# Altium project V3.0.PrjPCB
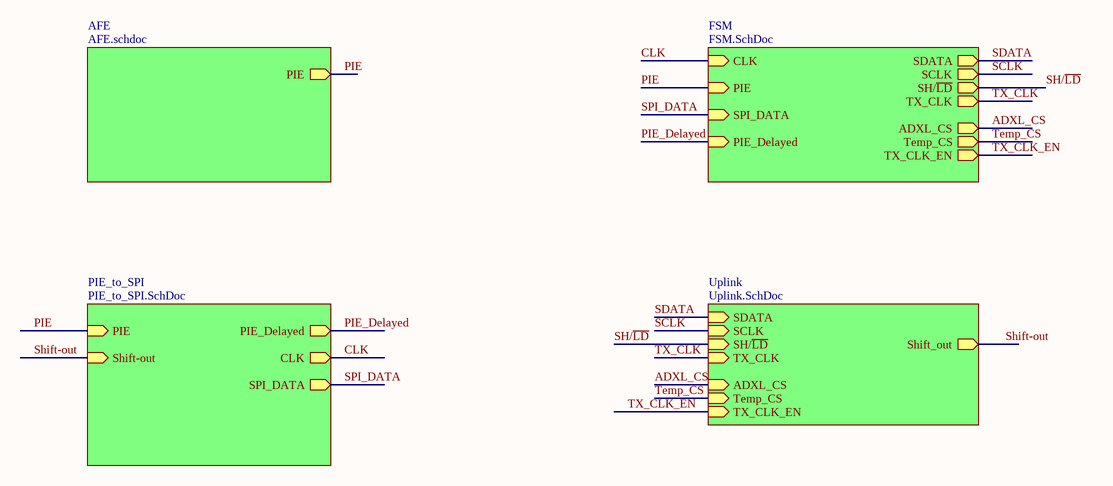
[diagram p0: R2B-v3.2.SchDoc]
5 sheets, 119 parts. Net scope: hierarchical (ports join the sheet entries above them; power ports are global).
Board file: 10.17.PcbDoc
Sheets:
  R2B-v3.2.SchDoc
    AFE = AFE.schdoc
    PIE_to_SPI = PIE_to_SPI.SchDoc
    FSM = FSM.SchDoc
    Uplink = Uplink.SchDoc

## Sheet R2B-v3.2.SchDoc
size A4; Date: 2019-11-16; Address1: Chong Zhang; Address2: Yihang Song; Revision: 3.2; SheetNumber: 1; SheetTotal: 5; Author1: Chong Zhang; Author2: Yihang Song

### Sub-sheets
AFE = AFE.schdoc: PIE (out)
FSM = FSM.SchDoc: CLK (in), PIE (in), SPI_DATA (in), PIE_Delayed (in), SDATA (out), SCLK (out), SH/~{LD} (out), TX_CLK (out), ADXL_CS (out), Temp_CS (out), TX_CLK_EN (out)
PIE_to_SPI = PIE_to_SPI.SchDoc: PIE (in), PIE_Delayed (out), CLK (out), SPI_DATA (out), Shift-out (in)
Uplink = Uplink.SchDoc: SDATA (in), SCLK (in), SH/~{LD} (in), TX_CLK (in), ADXL_CS (in), Temp_CS (in), Shift_out (out), TX_CLK_EN (in)

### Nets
ADXL_CS: sheet FSM/ADXL_CS, sheet Uplink/ADXL_CS
CLK: sheet PIE_to_SPI/CLK, sheet FSM/CLK
PIE: sheet AFE/PIE, sheet PIE_to_SPI/PIE, sheet FSM/PIE
PIE_Delayed: sheet PIE_to_SPI/PIE_Delayed, sheet FSM/PIE_Delayed
SCLK: sheet FSM/SCLK, sheet Uplink/SCLK
SDATA: sheet FSM/SDATA, sheet Uplink/SDATA
SH/~{LD}: sheet FSM/SH/~{LD}, sheet Uplink/SH/~{LD}
Shift-out: sheet PIE_to_SPI/Shift-out, sheet Uplink/Shift_out
SPI_DATA: sheet PIE_to_SPI/SPI_DATA, sheet FSM/SPI_DATA
Temp_CS: sheet FSM/Temp_CS, sheet Uplink/Temp_CS
TX_CLK: sheet FSM/TX_CLK, sheet Uplink/TX_CLK
TX_CLK_EN: sheet FSM/TX_CLK_EN, sheet Uplink/TX_CLK_EN

## Sheet AFE.schdoc
size A4; Date: 2019-11-16; Address1: Chong Zhang; Address2: Yihang Song; Revision: 3.2; SheetNumber: 2; SheetTotal: 5
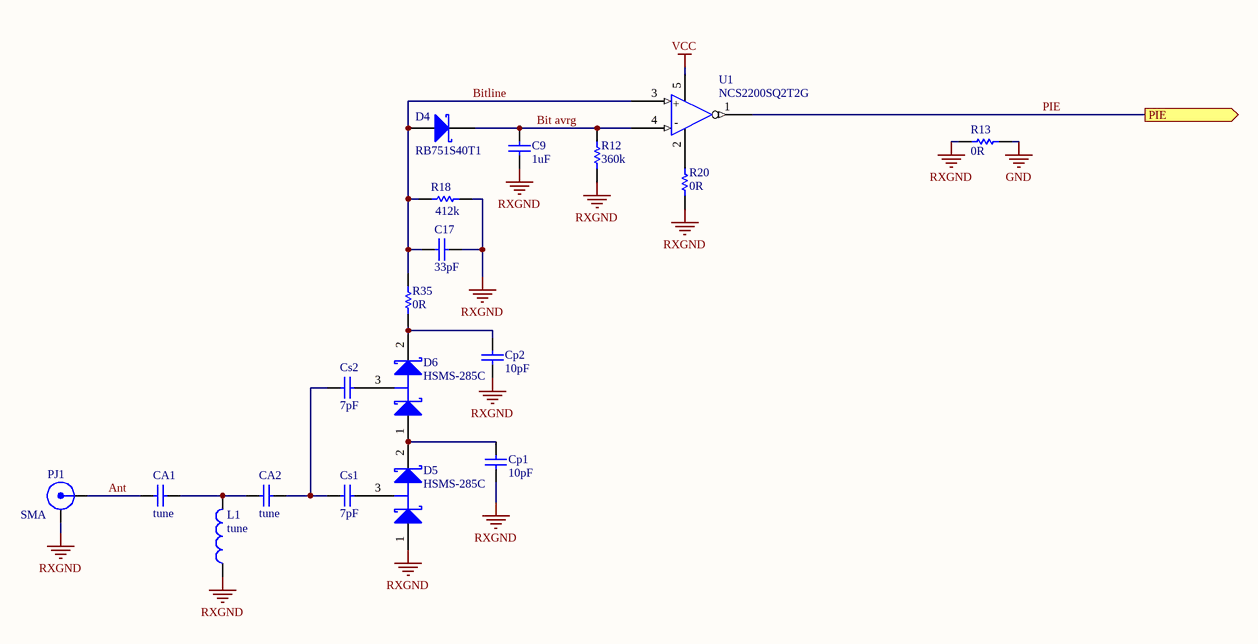
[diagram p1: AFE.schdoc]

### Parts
C9  value 1uF  [0402]  (hidden comment: Ceramic_Chip_Capacitor)
C17  value 33pF  [0402]  (hidden comment: Ceramic_Chip_Capacitor)
CA1  value tune  [0603]  (hidden comment: Ceramic Chip Capacitor)
CA2  value tune  [0603]  (hidden comment: Ceramic Chip Capacitor)
Cp1  value 10pF  [0402]  (hidden comment: Ceramic_Chip_Capacitor)
Cp2  value 10pF  [0402]  (hidden comment: Ceramic_Chip_Capacitor)
Cs1  value 7pF  [0402]  (hidden comment: Ceramic_Chip_Capacitor)
Cs2  value 7pF  [0402]  (hidden comment: Ceramic_Chip_Capacitor)
D4  RB751S40T1  [SOD-523]
D5  HSMS-285C  [SOT-323, HSMS-285C]
D6  HSMS-285C  [SOT-323, HSMS-285C]
L1  value tune  [0603]  (hidden comment: Inductor)
PJ1  SMA  [SMA]
R12  value 360k  [0603]  (hidden comment: Resistor)
R13  value 0R  [0402]  (hidden comment: Resistor)
R18  value 412k  [0603]  (hidden comment: Resistor)
R20  value 0R  [0402]  (hidden comment: Resistor)
R35  value 0R  [0603]  (hidden comment: Resistor)
U1  NCS2200SQ2T2G  [sc70-5]

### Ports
PIE (out)

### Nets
GND: R13.1
RXGND: C9.2 C17.2 Cp1.2 Cp2.2 D5.1(A) L1.1 PJ1.2(Y) R12.1 R13.2 R18.2 R20.2
VCC: U1.5(VDD)
Ant: CA1.1 PJ1.1(X)
Bit avrg: C9.1 D4.1(K) R12.2 U1.4(In-)
Bitline: C17.1 D4.2(A) R18.1 R35.2 U1.3(IN+)
PIE: U1.1(OUT) ; port PIE
NetCA1_2: CA1.2 CA2.1 L1.2
NetCA2_2: CA2.2 Cs1.1 Cs2.1
NetCp1_1: Cp1.1 D5.2(K) D6.1(A)
NetCp2_1: Cp2.1 D6.2(K) R35.1
NetCs1_2: Cs1.2 D5.3(C)
NetCs2_2: Cs2.2 D6.3(C)
NetR20_1: R20.1 U1.2(Gnd)

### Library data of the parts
C9 C17 Cp1 Cp2 Cs1 Cs2 = Ceramic_Chip_Capacitor: Ceramic Capacitor - Standard; Note: Footprint corresponds to dimensions for bulk cassette packaging. This case size has tightened tolerances.
CA1 CA2 = Ceramic Chip Capacitor: Ceramic Capacitor - Standard; DNS: Do Not Stuff Part
D4 = Schottky Diode
D5 D6 = HSMS-285C: Agilent Schottky Diode, Bridge Quad, HSMS-285C
R12 R13 R18 R20 R35 = Resistor: Thick Film Resistor
U1 = NCS2200SQ2T2G: On Semi 10uA Comparator

## Sheet PIE_to_SPI.SchDoc
size A4; Date: 2019-11-16; Address1: Chong Zhang; Address2: Yihang Song; Revision: 3.2; SheetNumber: 3; SheetTotal: 5
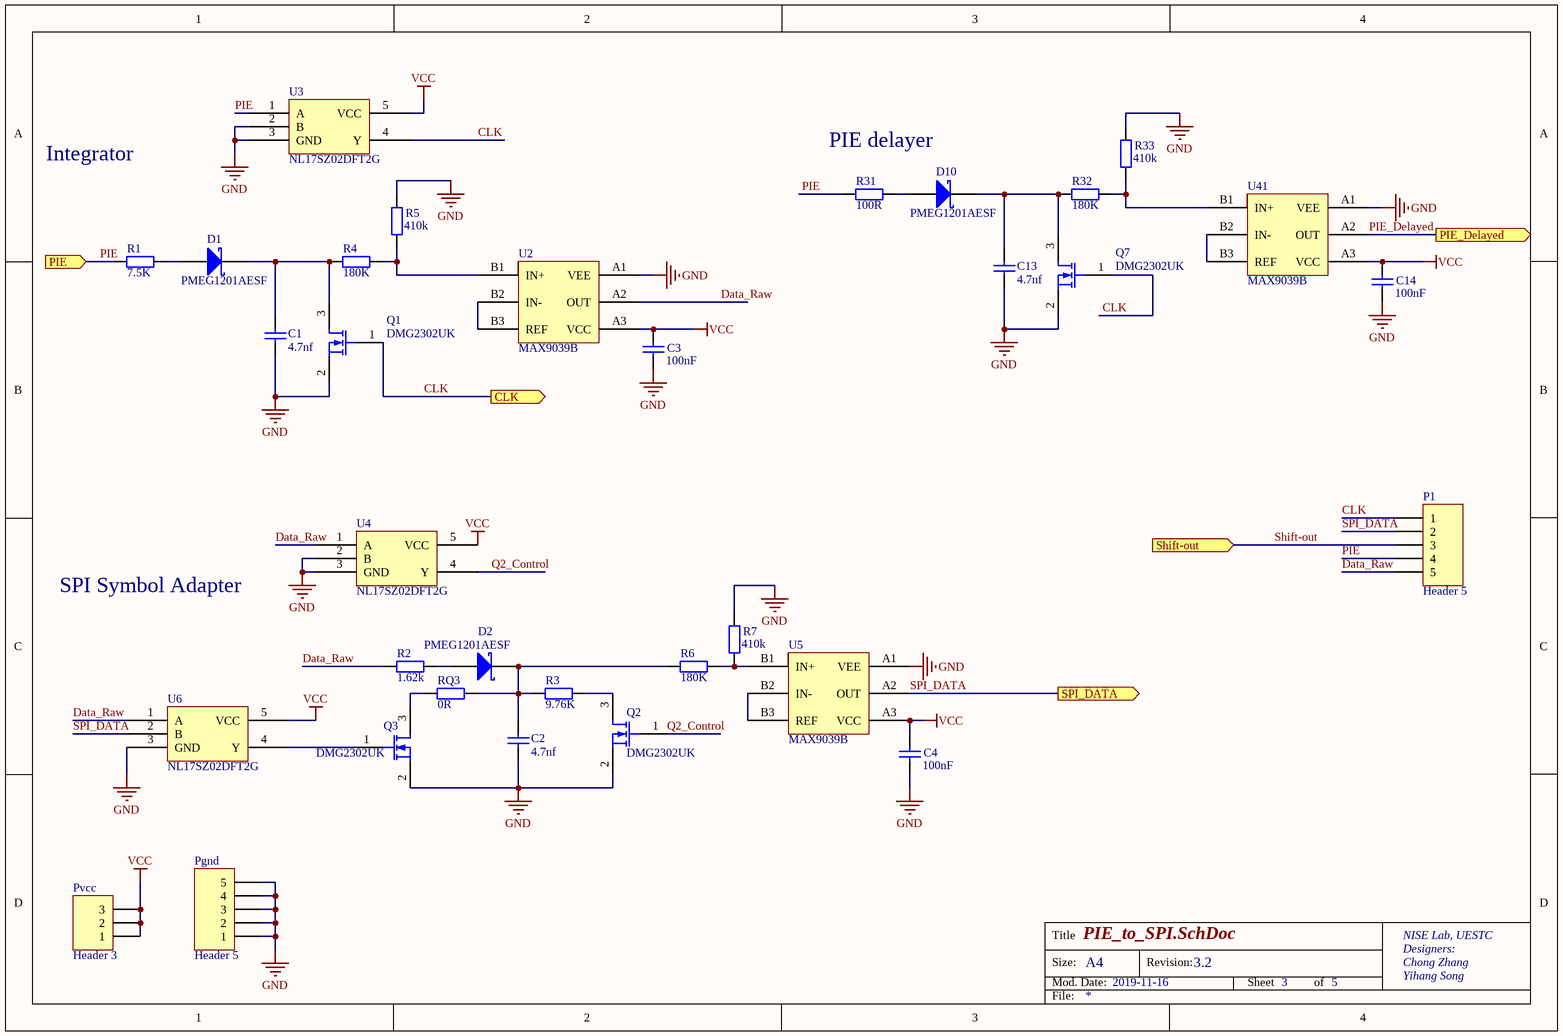
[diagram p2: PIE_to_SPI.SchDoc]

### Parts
C1  4.7nf  [6-0805_N]
C2  4.7nf  [6-0805_N]
C3  100nF  [6-0805_N]
C4  100nF  [6-0805_N]
C13  4.7nf  [6-0805_N]
C14  100nF  [6-0805_N]
D1  PMEG1201AESF  [DIODE]
D2  PMEG1201AESF  [DIODE]
D10  PMEG1201AESF  [DIODE]
P1  Header 5  [HDR1X5]
Pgnd  Header 5  [HDR1X5]
Pvcc  Header 3  [HDR1X3]
Q1  DMG2302UK  [NMOS-DMG2302UK]
Q2  DMG2302UK  [NMOS-DMG2302UK]
Q3  DMG2302UK  [NMOS-DMG2302UK]
Q7  DMG2302UK  [NMOS-DMG2302UK]
R1  7.5K  [6-0805_N]
R2  1.62k  [6-0805_N]
R3  9.76K  [6-0805_N]
R4  180K  [6-0805_N]
R5  410k  [6-0805_N]
R6  180K  [6-0805_N]
R7  410k  [6-0805_N]
R31  100R  [6-0805_N]
R32  180K  [6-0805_N]
R33  410k  [6-0805_N]
RQ3  0R  [6-0805_N]
U2  MAX9039B  [BGA6-UCSP6]
U3  NL17SZ02DFT2G  [SC-88A (SC-70-5/SOT-353)]
U4  NL17SZ02DFT2G  [SC-88A (SC-70-5/SOT-353)]
U5  MAX9039B  [BGA6-UCSP6]
U6  NL17SZ02DFT2G  [SC-88A (SC-70-5/SOT-353)]
U41  MAX9039B  [BGA6-UCSP6]

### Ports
CLK (out), PIE (in), PIE_Delayed (out), Shift-out (in), SPI_DATA (out)

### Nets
GND: C1.1 C2.1 C3.1 C4.1 C13.1 C14.1 Pgnd.1 Pgnd.2 Pgnd.3 Pgnd.4 Pgnd.5 Q1.2(S) Q2.2(S) Q3.2(S) Q7.2(S) R5.2 R7.2 R33.2 U2.A1(VEE) U3.2(B) U3.3(GND) U4.2(B) U4.3(GND) U5.A1(VEE) U6.3(GND) U41.A1(VEE)
VCC: C3.2 C4.2 C14.2 Pvcc.1 Pvcc.2 Pvcc.3 U2.A3(VCC) U3.5(VCC) U4.5(VCC) U5.A3(VCC) U6.5(VCC) U41.A3(VCC)
CLK: P1.1 Q1.1(G) Q7.1(G) U3.4(Y) ; port CLK
Data_Raw: P1.5 R2.1 U2.A2(OUT) U4.1(A) U6.1(A)
PIE: P1.4 R1.1 R31.1 U3.1(A) ; port PIE
PIE_Delayed: U41.A2(OUT) ; port PIE_Delayed
Q2_Control: Q2.1(G) U4.4(Y)
Shift-out: P1.3 ; port Shift-out
SPI_DATA: P1.2 U5.A2(OUT) U6.2(B) ; port SPI_DATA
NetC1_2: C1.2 D1.1(C) Q1.3(D) R4.1
NetC2_2: C2.2 D2.1(C) R3.1 R6.1 RQ3.2
NetC13_2: C13.2 D10.1(C) Q7.3(D) R32.1
NetD1_2: D1.2(A) R1.2
NetD2_2: D2.2(A) R2.2
NetD10_2: D10.2(A) R31.2
NetQ2_3: Q2.3(D) R3.2
NetQ3_1: Q3.1(G) U6.4(Y)
NetQ3_3: Q3.3(D) RQ3.1
NetR4_2: R4.2 R5.1 U2.B1(IN+)
NetR6_2: R6.2 R7.1 U5.B1(IN+)
NetR32_2: R32.2 R33.1 U41.B1(IN+)
NetU2_B2: U2.B2(IN-) U2.B3(REF)
NetU5_B2: U5.B2(IN-) U5.B3(REF)
NetU41_B2: U41.B2(IN-) U41.B3(REF)

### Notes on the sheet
- Integrator
- PIE delayer
- SPI Symbol Adapter

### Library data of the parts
C1-C4 C13 C14 = Cap: Capacitor; Value: 100pF
D1 D2 D10 = DIODE: Schottky Diode
P1 Pgnd = Header 5: Header, 5-Pin
Pvcc = Header 3: Header, 3-Pin
Q1-Q3 Q7 = MOSFET-N: N-Channel MOSFET; PackageDocument: 1995/1996
R1-R7 R31-R33 RQ3 = Res2: Resistor; Value: 1K
U2 U5 U41 = Comparator
U3 U4 U6 = NOR GATE

## Sheet FSM.SchDoc
size C; Date: 2019-11-16; Address1: Chong Zhang; Address2: Yihang Song; Revision: 3.2; SheetNumber: 4; SheetTotal: 5
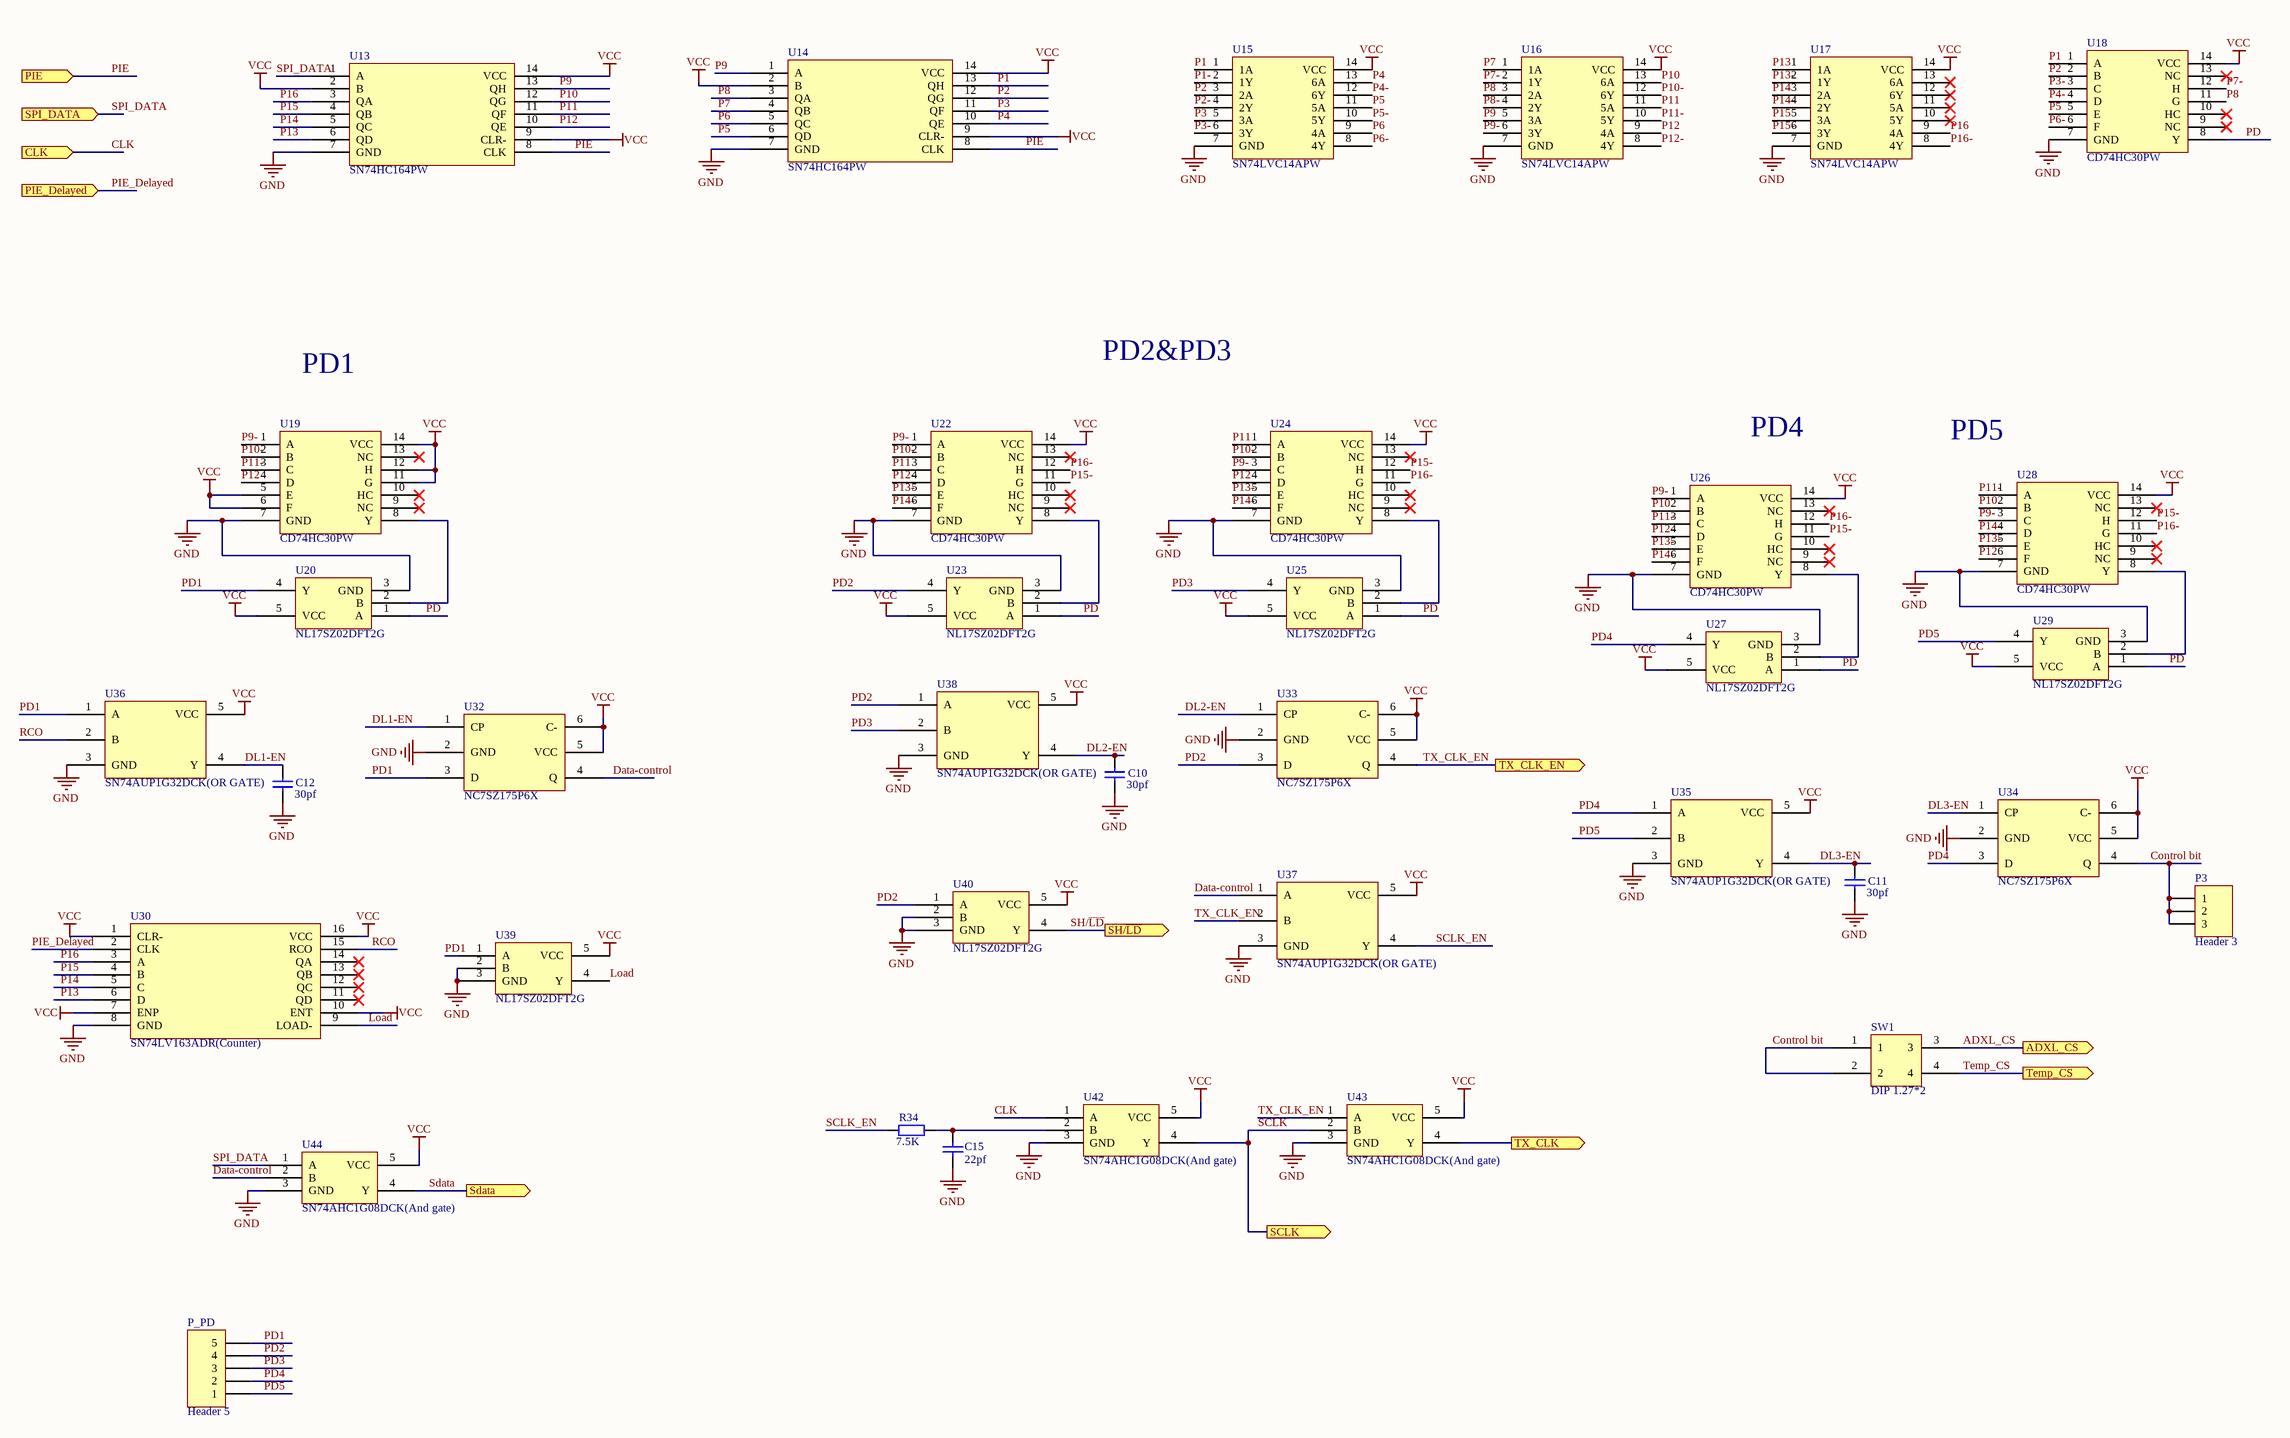
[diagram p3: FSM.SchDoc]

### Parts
C10  30pf  [6-0805_N]
C11  30pf  [6-0805_N]
C12  30pf  [6-0805_N]
C15  22pf  [6-0805_N]
P3  Header 3  [HDR1X3]
P_PD  Header 5  [HDR1X5]
R34  7.5K  [6-0805_N]
SW1  DIP 1.27*2  [KEY1.27*2new]
U13  SN74HC164PW  [Tssop14(shift8)]
U14  SN74HC164PW  [Tssop14(shift8)]
U15  SN74LVC14APW  [Tssop14(shift8)]
U16  SN74LVC14APW  [Tssop14(shift8)]
U17  SN74LVC14APW  [Tssop14(shift8)]
U18  CD74HC30PW  [Tssop14(shift8)]
U19  CD74HC30PW  [Tssop14(shift8)]
U20  NL17SZ02DFT2G  [SC-88A (SC-70-5/SOT-353)]
U22  CD74HC30PW  [Tssop14(shift8)]
U23  NL17SZ02DFT2G  [SC-88A (SC-70-5/SOT-353)]
U24  CD74HC30PW  [Tssop14(shift8)]
U25  NL17SZ02DFT2G  [SC-88A (SC-70-5/SOT-353)]
U26  CD74HC30PW  [Tssop14(shift8)]
U27  NL17SZ02DFT2G  [SC-88A (SC-70-5/SOT-353)]
U28  CD74HC30PW  [Tssop14(shift8)]
U29  NL17SZ02DFT2G  [SC-88A (SC-70-5/SOT-353)]
U30  SN74LV163ADR(Counter)  [SOIC127P600X265-16N]
U32  NC7SZ175P6X  [SC-70]
U33  NC7SZ175P6X  [SC-70]
U34  NC7SZ175P6X  [SC-70]
U35  SN74AUP1G32DCK(OR GATE)  [SN74AUP1G32DCK（OR-gate-SC70-DCK）]
U36  SN74AUP1G32DCK(OR GATE)  [SN74AUP1G32DCK（OR-gate-SC70-DCK）]
U37  SN74AUP1G32DCK(OR GATE)  [SN74AUP1G32DCK（OR-gate-SC70-DCK）]
U38  SN74AUP1G32DCK(OR GATE)  [SN74AUP1G32DCK（OR-gate-SC70-DCK）]
U39  NL17SZ02DFT2G  [SC-88A (SC-70-5/SOT-353)]
U40  NL17SZ02DFT2G  [SC-88A (SC-70-5/SOT-353)]
U42  SN74AHC1G08DCK(And gate)  [AND-gate-SC70-DCK]
U43  SN74AHC1G08DCK(And gate)  [AND-gate-SC70-DCK]
U44  SN74AHC1G08DCK(And gate)  [AND-gate-SC70-DCK]

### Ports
ADXL_CS (out), CLK (in), PIE (in), PIE_Delayed (in), SCLK (out), Sdata (out), SH/~{LD} (out), SPI_DATA (in), Temp_CS (out), TX_CLK (out), TX_CLK_EN (out)

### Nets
GND: C10.1 C11.1 C12.1 C15.1 U13.7(GND) U14.7(GND) U15.7(GND) U16.7(GND) U17.7(GND) U18.7(GND) U19.7(GND) U20.3(GND) U22.7(GND) U23.3(GND) U24.7(GND) U25.3(GND) U26.7(GND) U27.3(GND) U28.7(GND) U29.3(GND) U30.8(GND) U32.2(GND) U33.2(GND) U34.2(GND) U35.3(GND) U36.3(GND) U37.3(GND) U38.3(GND) U39.2(B) U39.3(GND) U40.2(B) U40.3(GND) U42.3(GND) U43.3(GND) U44.3(GND)
VCC: U13.2(B) U13.9(CLR-) U13.14(VCC) U14.2(B) U14.9(CLR-) U14.14(VCC) U15.14(VCC) U16.14(VCC) U17.14(VCC) U18.14(VCC) U19.5(E) U19.6(F) U19.11(G) U19.12(H) U19.14(VCC) U20.5(VCC) U22.14(VCC) U23.5(VCC) U24.14(VCC) U25.5(VCC) U26.14(VCC) U27.5(VCC) U28.14(VCC) U29.5(VCC) U30.1(CLR-) U30.7(ENP) U30.10(ENT) U30.16(VCC) U32.5(VCC) U32.6(C-) U33.5(VCC) U33.6(C-) U34.5(VCC) U34.6(C-) U35.5(VCC) U36.5(VCC) U37.5(VCC) U38.5(VCC) U39.5(VCC) U40.5(VCC) U42.5(VCC) U43.5(VCC) U44.5(VCC)
ADXL_CS: SW1.3 ; port ADXL_CS
CLK: U42.1(A) ; port CLK
Control bit: P3.1 P3.2 P3.3 SW1.1 SW1.2 U34.4(Q)
Data-control: U32.4(Q) U37.1(A) U44.2(B)
DL1-EN: C12.2 U32.1(CP) U36.4(Y)
DL2-EN: C10.2 U33.1(CP) U38.4(Y)
DL3-EN: C11.2 U34.1(CP) U35.4(Y)
Load: U30.9(LOAD-) U39.4(Y)
P1: U14.13(QH) U15.1(1A) U18.1(A)
P1-: U15.2(1Y)
P2: U14.12(QG) U15.3(2A) U18.2(B)
P2-: U15.4(2Y)
P3: U14.11(QF) U15.5(3A)
P3-: U15.6(3Y) U18.3(C)
P4: U14.10(QE) U15.13(6A)
P4-: U15.12(6Y) U18.4(D)
P5: U14.6(QD) U15.11(5A) U18.5(E)
P5-: U15.10(5Y)
P6: U14.5(QC) U15.9(4A)
P6-: U15.8(4Y) U18.6(F)
P7: U14.4(QB) U16.1(1A)
P7-: U16.2(1Y) U18.12(H)
P8: U14.3(QA) U16.3(2A) U18.11(G)
P8-: U16.4(2Y)
P9: U13.13(QH) U14.1(A) U16.5(3A)
P9-: U16.6(3Y) U19.1(A) U22.1(A) U24.3(C) U26.1(A) U28.3(C)
P10: U13.12(QG) U16.13(6A) U26.2(B) U28.2(B)
P10-: U16.12(6Y) U19.2(B) U22.2(B) U24.2(B)
P11: U13.11(QF) U16.11(5A) U22.3(C) U24.1(A)
P11-: U16.10(5Y) U19.3(C) U26.3(C) U28.1(A)
P12: U13.10(QE) U16.9(4A) U19.4(D) U24.4(D) U28.6(F)
P12-: U16.8(4Y) U22.4(D) U26.4(D)
P13: U13.6(QD) U17.1(1A) U30.6(D)
P13-: U17.2(1Y) U22.5(E) U24.5(E) U26.5(E) U28.5(E)
P14: U13.5(QC) U17.3(2A) U30.5(C)
P14-: U17.4(2Y) U22.6(F) U24.6(F) U26.6(F) U28.4(D)
P15: U13.4(QB) U17.5(3A) U30.4(B)
P15-: U17.6(3Y) U22.11(G) U24.12(H) U26.11(G) U28.12(H)
P16: U13.3(QA) U17.9(4A) U30.3(A)
P16-: U17.8(4Y) U22.12(H) U24.11(G) U26.12(H) U28.11(G)
PD: U18.8(Y) U20.1(A) U23.1(A) U25.1(A) U27.1(A) U29.1(A)
PD1: P_PD.5 U20.4(Y) U32.3(D) U36.1(A) U39.1(A)
PD2: P_PD.4 U23.4(Y) U33.3(D) U38.1(A) U40.1(A)
PD3: P_PD.3 U25.4(Y) U38.2(B)
PD4: P_PD.2 U27.4(Y) U34.3(D) U35.1(A)
PD5: P_PD.1 U29.4(Y) U35.2(B)
PIE: U13.8(CLK) U14.8(CLK) ; port PIE
PIE_Delayed: U30.2(CLK) ; port PIE_Delayed
RCO: U30.15(RCO) U36.2(B)
SCLK: U42.4(Y) U43.2(B) ; port SCLK
SCLK_EN: R34.1 U37.4(Y)
SDATA: U44.4(Y) ; port Sdata
SH/~{LD}: U40.4(Y) ; port SH/~{LD}
SPI_DATA: U13.1(A) U44.1(A) ; port SPI_DATA
Temp_CS: SW1.4 ; port Temp_CS
TX_CLK: U43.4(Y) ; port TX_CLK
TX_CLK_EN: U33.4(Q) U37.2(B) U43.1(A) ; port TX_CLK_EN
NetC15_2: C15.2 R34.2 U42.2(B)
NetU19_8: U19.8(Y) U20.2(B)
NetU22_8: U22.8(Y) U23.2(B)
NetU24_8: U24.8(Y) U25.2(B)
NetU26_8: U26.8(Y) U27.2(B)
NetU28_8: U28.8(Y) U29.2(B)

Not connected (* = marked no-connect by the designer): U17 10(5Y)* 11(5A)* 12(6Y)* 13(6A)*; U18 9(NC)* 10(HC)* 13(NC)*; U19 9(NC)* 10(HC)* 13(NC)*; U22 9(NC)* 10(HC)* 13(NC)*; U24 9(NC)* 10(HC)* 13(NC)*; U26 9(NC)* 10(HC)* 13(NC)*; U28 9(NC)* 10(HC)* 13(NC)*; U30 11(QD)* 12(QC)* 13(QB)* 14(QA)*

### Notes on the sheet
- PD1
- PD2&PD3
- PD4
- PD5

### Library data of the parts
C10-C12 C15 = Cap: Capacitor; Value: 100pF
P3 = Header 3: Header, 3-Pin
P_PD = Header 5: Header, 5-Pin
R34 = Res2: Resistor; Value: 1K
SW1 = KEY1.27*2
U13 U14 = SN74HC164
U20 U23 U25 U27 U29 U39 U40 = NOR GATE
U30 = SN74LV163APW(Counter)

## Sheet Uplink.SchDoc
size A4; Date: 2019-11-16; Address1: Chong Zhang; Address2: Yihang Song; Revision: 3.2; SheetNumber: 5; SheetTotal: 5
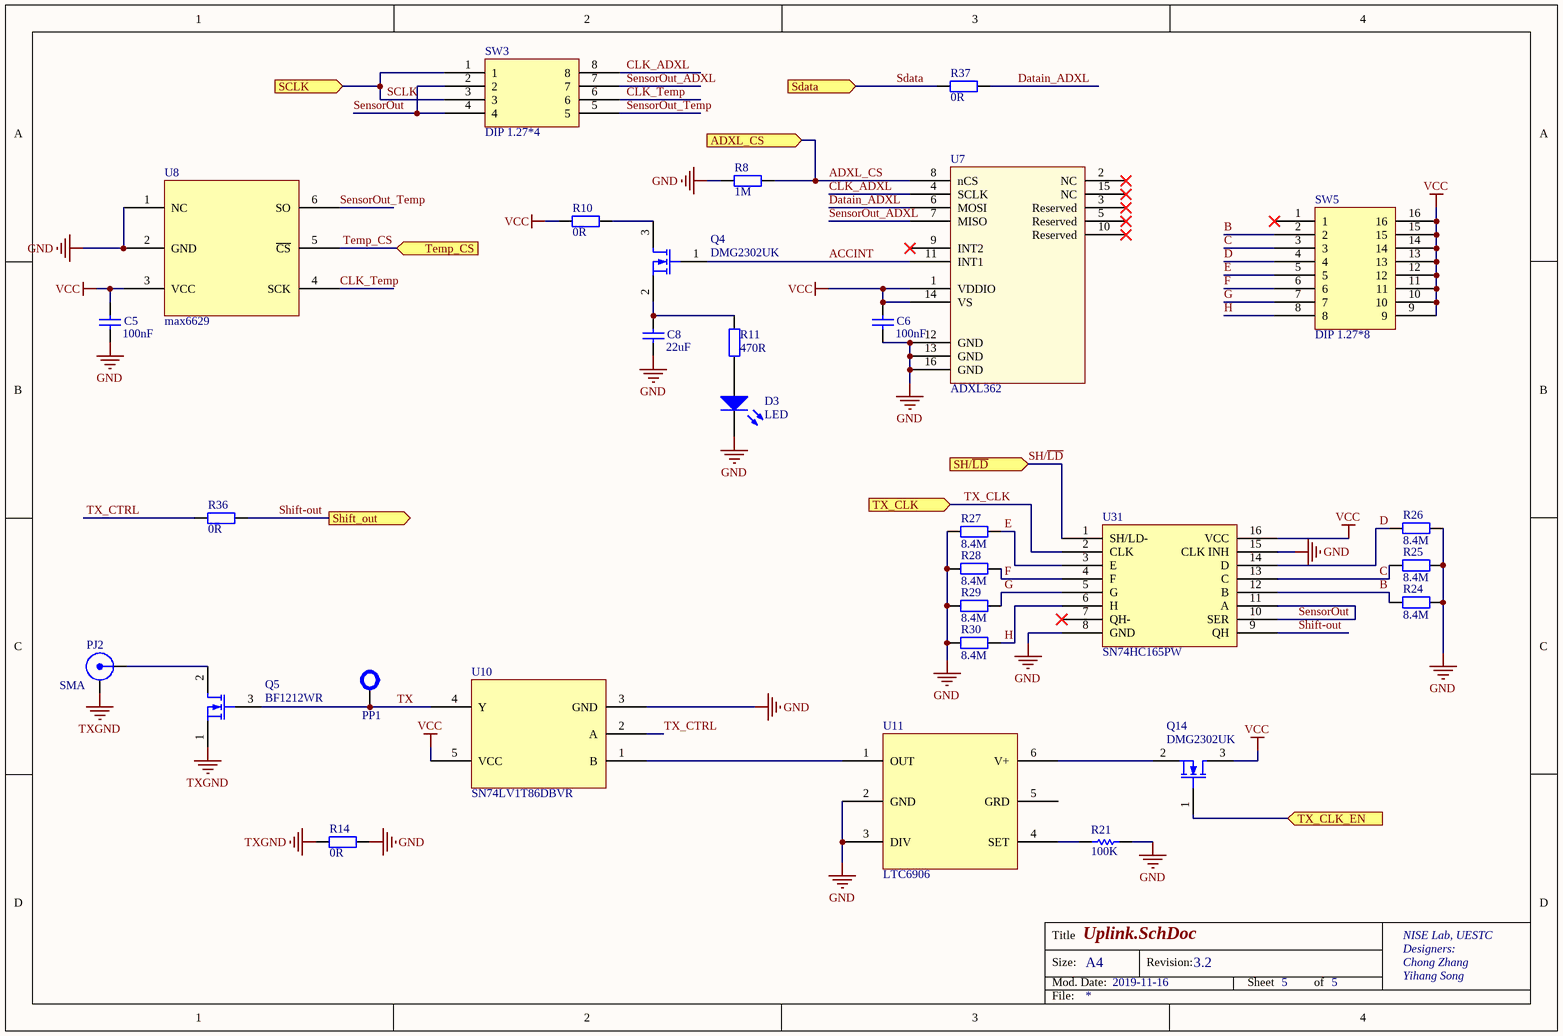
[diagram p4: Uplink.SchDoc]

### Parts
C5  100nF  [6-0805_N]
C6  100nF  [6-0805_N]
C8  22uF  [6-0805_N]
D3  LED  [6-0805_N]
PJ2  SMA  [SMA]
PP1  Probe Point  [Probe Point]  (value not drawn)
Q4  DMG2302UK  [NMOS-DMG2302UK]
Q5  BF1212WR  [sot343r]
Q14  DMG2302UK  [NMOS-DMG2302UK]
R8  1M  [6-0805_N]
R10  0R  [6-0805_N]
R11  470R  [6-0805_N]
R14  0R  [6-0805_N]
R21  Vaule: 100K  [6-0805_M]  (hidden comment: Resistor)
R24  8.4M  [6-0805_N]
R25  8.4M  [6-0805_N]
R26  8.4M  [6-0805_N]
R27  8.4M  [6-0805_N]
R28  8.4M  [6-0805_N]
R29  8.4M  [6-0805_N]
R30  8.4M  [6-0805_N]
R36  0R  [6-0805_N]
R37  0R  [6-0805_N]
SW3  DIP 1.27*4  [KEY1.27*4]
SW5  DIP 1.27*8  [KEY1.27*8]
U7  ADXL362  [ADXL362]
U8  max6629  [MAX6629-6632]
U10  SN74LV1T86DBVR  [SOT-23-5 -D]
U11  LTC6906  [LTC6906]
U31  SN74HC165PW  [TSSOP16(COUNTER)]

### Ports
ADXL_CS (in), SCLK (in), Sdata (in), SH/~{LD} (in), Shift_out (out), Temp_CS (in), TX_CLK (in), TX_CLK_EN (in)

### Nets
GND: C5.1 C6.1 C8.1 D3.2(K) R8.1 R14.2 R21.1 R24.2 R25.2 R26.2 R27.1 R28.1 R29.1 R30.1 U7.12(GND) U7.13(GND) U7.16(GND) U8.1(NC) U8.2(GND) U10.3(GND) U11.2(GND) U11.3(DIV) U31.8(GND) U31.15(CLK_INH)
TXGND: PJ2.2(Y) Q5.1(S) R14.1
VCC: C5.2 C6.2 Q14.3(D) R10.1 SW5.9 SW5.10 SW5.11 SW5.12 SW5.13 SW5.14 SW5.15 SW5.16 U7.1(VDDIO) U7.14(VS) U8.3(VCC) U10.5(VCC) U31.16(VCC)
ACCINT: Q4.1(G) U7.11(INT1)
ADXL_CS: R8.2 U7.8(nCS) ; port ADXL_CS
B: R24.1 SW5.2 U31.12(B)
C: R25.1 SW5.3 U31.13(C)
CLK_ADXL: SW3.8 U7.4(SCLK)
CLK_Temp: SW3.6 U8.4(SCK)
D: R26.1 SW5.4 U31.14(D)
Datain_ADXL: R37.2 U7.6(MOSI)
E: R27.2 SW5.5 U31.3(E)
F: R28.2 SW5.6 U31.4(F)
G: R29.2 SW5.7 U31.5(G)
H: R30.2 SW5.8 U31.6(H)
SCLK: SW3.1 SW3.3 ; port SCLK
SDATA: R37.1 ; port Sdata
SensorOut: SW3.2 SW3.4 U31.10(SER) U31.11(A)
SensorOut_ADXL: SW3.7 U7.7(MISO)
SensorOut_Temp: SW3.5 U8.6(SO)
SH/~{LD}: U31.1(SH/LD-) ; port SH/~{LD}
Shift-out: R36.2 U31.9(QH) ; port Shift_out
Temp_CS: U8.5(~{CS}) ; port Temp_CS
TX: PP1.0 Q5.3(G) U10.4(Y)
TX_CLK: U31.2(CLK) ; port TX_CLK
TX_CLK_EN: Q14.1(G) ; port TX_CLK_EN
TX_CTRL: R36.1 U10.2(A)
NetC8_2: C8.2 Q4.2(S) R11.2
NetD3_1: D3.1(A) R11.1
NetPJ2_1: PJ2.1(X) Q5.2(D)
NetQ4_3: Q4.3(D) R10.2
NetQ14_2: Q14.2(S) U11.6(V+)
NetR21_2: R21.2 U11.4(SET)
NetU10_1: U10.1(B) U11.1(OUT)

Not connected (* = marked no-connect by the designer): SW5 1*; U7 2(NC)* 3(Reserved)* 5(Reserved)* 9(INT2)* 10(Reserved)* 15(NC)*; U11 5(GRD); U31 7(QH-)*

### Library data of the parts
C5 C6 C8 = Cap: Capacitor; Value: 100pF
D3 = LED0: Typical INFRARED GaAs LED
PP1 = Probe Point: Probe Point for debug
Q4 Q14 = MOSFET-N: as Q1 on sheet PIE_to_SPI
Q5 = BF1212
R8 R10 R11 R14 R24-R30 R36 R37 = Res2: Resistor; Value: 1K
R21 = Resistor: Thick Film Resistor
SW3 = KEY1.27*4
SW5 = KEY1.27*8
U7 = ADXL362: Analog Devices low power accelerometer
U10 = XOR GATE

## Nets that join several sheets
GND: AFE (R13.1), PIE_to_SPI (26 pins), FSM (35 pins), Uplink (24 pins)
VCC: AFE (U1.5), PIE_to_SPI (12 pins), FSM (43 pins), Uplink (17 pins)
ADXL_CS: FSM (SW1.3), Uplink (R8.2 U7.8)
CLK: PIE_to_SPI (P1.1 Q1.1 Q7.1 U3.4), FSM (U42.1)
PIE: AFE (U1.1), PIE_to_SPI (P1.4 R1.1 R31.1 U3.1), FSM (U13.8 U14.8)
PIE_Delayed: PIE_to_SPI (U41.A2), FSM (U30.2)
SCLK: FSM (U42.4 U43.2), Uplink (SW3.1 SW3.3)
SDATA: FSM (U44.4), Uplink (R37.1)
SH/~{LD}: FSM (U40.4), Uplink (U31.1)
Shift-out: PIE_to_SPI (P1.3), Uplink (R36.2 U31.9)
SPI_DATA: PIE_to_SPI (P1.2 U5.A2 U6.2), FSM (U13.1 U44.1)
Temp_CS: FSM (SW1.4), Uplink (U8.5)
TX_CLK: FSM (U43.4), Uplink (U31.2)
TX_CLK_EN: FSM (U33.4 U37.2 U43.1), Uplink (Q14.1)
